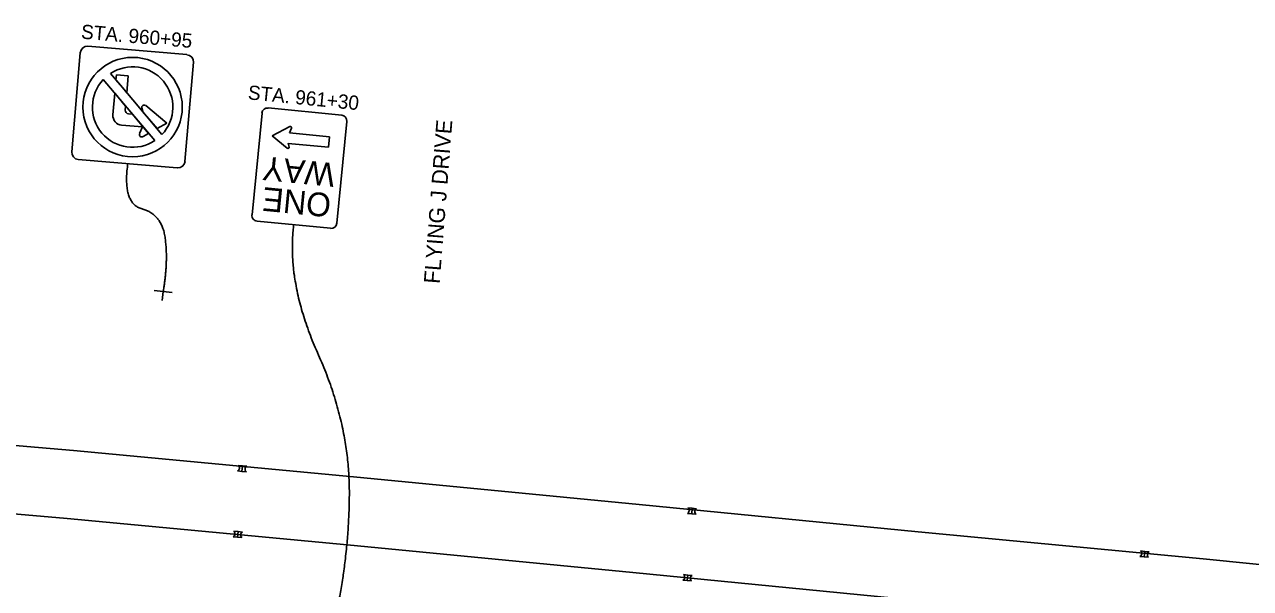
# Model space of a CAD drawing. Extents: x 1847379 to 1850904, y 217032 to 220169.
# Drawn here: x 1850210.2 to 1850426.1, y 218769.3 to 218868.6 of the extents above; entities that cross this region are included whole.
import ezdxf

# ---------------------------------------------------------------- set-up
doc = ezdxf.new("R2010")
doc.units = 0
for name, color, linetype in [('PM_P_Cells', 7, 'Continuous'), ('PM_P_Edge_Line', 7, 'Continuous'), ('PM_P_Lane_Line', 7, 'Continuous'), ('SN_X_Public', 7, 'Continuous'), ('SN_X_Text', 7, 'Continuous')]:
    doc.layers.add(name, color=color, linetype=linetype)

msp = doc.modelspace()

# ---------------------------------------------------------------- linework, layer by layer
at = {"layer": 'PM_P_Cells'}
for p, q in [((1850247.75, 218790.01), (1850248.51, 218789.94)), ((1850247.75, 218790.01), (1850248.51, 218789.94)), ((1850248.6, 218790.91), (1850247.83, 218790.98)), ((1850247.83, 218790.98), (1850248.6, 218790.91)), ((1850248.51, 218789.94), (1850248.6, 218790.91)), ((1850248.51, 218789.94), (1850249.28, 218789.87)), ((1850248.6, 218790.91), (1850249.37, 218790.84)), ((1850327.78, 218783.43), (1850327.01, 218783.5)), ((1850327.01, 218783.5), (1850327.78, 218783.43)), ((1850327.69, 218782.45), (1850327.78, 218783.43)), ((1850327.78, 218783.43), (1850328.55, 218783.36)), ((1850326.92, 218782.52), (1850327.69, 218782.45)), ((1850326.92, 218782.52), (1850327.69, 218782.45)), ((1850327.69, 218782.45), (1850328.46, 218782.39)), ((1850247.83, 218779.33), (1850247.06, 218779.4)), ((1850247.06, 218779.4), (1850247.83, 218779.33)), ((1850247.74, 218778.36), (1850247.83, 218779.33)), ((1850247.83, 218779.33), (1850248.6, 218779.26)), ((1850246.97, 218778.42), (1850247.74, 218778.36)), ((1850246.97, 218778.42), (1850247.74, 218778.36)), ((1850247.74, 218778.36), (1850248.51, 218778.29)), ((1850406.6, 218774.95), (1850407.36, 218774.88)), ((1850406.6, 218774.95), (1850407.36, 218774.88)), ((1850407.45, 218775.85), (1850406.68, 218775.92)), ((1850406.68, 218775.92), (1850407.45, 218775.85)), ((1850407.36, 218774.88), (1850407.45, 218775.85)), ((1850407.36, 218774.88), (1850408.13, 218774.81)), ((1850407.45, 218775.85), (1850408.22, 218775.78)), ((1850326.14, 218770.79), (1850326.91, 218770.72)), ((1850326.14, 218770.79), (1850326.91, 218770.72)), ((1850327, 218771.69), (1850326.23, 218771.76)), ((1850326.23, 218771.76), (1850327, 218771.69)), ((1850326.91, 218770.72), (1850327, 218771.69)), ((1850326.91, 218770.72), (1850327.67, 218770.65)), ((1850327, 218771.69), (1850327.76, 218771.62))]:
    msp.add_line(p, q, dxfattribs=at)
for centre, start, end in [((1850247.49, 218790.52), 296.8063, 52.8586), ((1850247.49, 218790.52), 296.8063, 52.8586), ((1850249.63, 218790.33), 116.8063, 232.8586), ((1850326.66, 218783.04), 296.8063, 52.8586), ((1850326.66, 218783.04), 296.8063, 52.8586), ((1850328.81, 218782.84), 116.8063, 232.8586), ((1850246.71, 218778.94), 296.8063, 52.8586), ((1850246.71, 218778.94), 296.8063, 52.8586), ((1850248.86, 218778.74), 116.8063, 232.8586), ((1850406.34, 218775.46), 296.8063, 52.8586), ((1850406.34, 218775.46), 296.8063, 52.8586), ((1850408.48, 218775.27), 116.8063, 232.8586), ((1850325.88, 218771.3), 296.8063, 52.8586), ((1850325.88, 218771.3), 296.8063, 52.8586), ((1850328.02, 218771.11), 116.8063, 232.8586)]:
    msp.add_arc(centre, 0.576, start, end, dxfattribs=at)
at = {"layer": 'PM_P_Edge_Line'}
msp.add_lwpolyline([(1849889.22, 218821.46), (1849908.57, 218819.63), (1849959.34, 218815.75), (1850016.54, 218811.11), (1850069.2, 218806.62), (1850120.11, 218802.11), (1850169.53, 218797.86), (1850218.84, 218793.6), (1850268.16, 218788.98), (1850318.46, 218784.1), (1850367.53, 218779.29), (1850417.75, 218774.53), (1850467.84, 218769.49), (1850519.01, 218764.5), (1850567.74, 218759.83), (1850617.52, 218754.84), (1850666.94, 218749.6)], dxfattribs=at)
at = {"layer": 'PM_P_Lane_Line'}
msp.add_lwpolyline([(1849608.99, 218828.81), (1849660.31, 218825.18), (1849710.18, 218821.58), (1849761.09, 218817.87), (1849808.06, 218814.41), (1849858.45, 218811.1), (1849907.69, 218807.67), (1849958.4, 218803.79), (1850015.55, 218799.15), (1850068.16, 218794.66), (1850119.07, 218790.16), (1850168.5, 218785.91), (1850217.76, 218781.65), (1850267.02, 218777.03), (1850317.3, 218772.15), (1850366.38, 218767.35), (1850416.59, 218762.59), (1850466.65, 218757.55), (1850517.86, 218752.55), (1850566.57, 218747.88), (1850616.29, 218742.91), (1850664.9, 218737.75)], dxfattribs=at)
at = {"layer": 'SN_X_Public'}
for p, q in [((1850233.16, 218848.15), (1850224.09, 218858.9)), ((1850226.32, 218858.84), (1850226.4, 218859.74)), ((1850226.4, 218859.74), (1850226.32, 218858.84)), ((1850226.32, 218858.84), (1850227.45, 218857.51)), ((1850226.4, 218859.74), (1850228.47, 218859.57)), ((1850228.47, 218859.57), (1850226.4, 218859.74)), ((1850228.22, 218856.59), (1850228.47, 218859.57)), ((1850228.22, 218856.59), (1850228.47, 218859.57)), ((1850227.45, 218857.51), (1850228.22, 218856.59)), ((1850225.8, 218852.68), (1850226.12, 218856.49)), ((1850226.12, 218856.49), (1850225.8, 218852.68)), ((1850226.17, 218856.43), (1850226.12, 218856.49)), ((1850228.02, 218854.24), (1850226.17, 218856.43)), ((1850227.96, 218853.52), (1850228.02, 218854.24)), ((1850227.96, 218853.52), (1850228.02, 218854.24)), ((1850228.51, 218852.87), (1850229.23, 218852.81)), ((1850229.23, 218852.81), (1850228.51, 218852.87)), ((1850232.08, 218849.42), (1850229.23, 218852.81)), ((1850230.89, 218853.9), (1850231.03, 218853.28)), ((1850230.89, 218853.9), (1850231.03, 218853.28)), ((1850231.02, 218853.27), (1850233.56, 218850.26)), ((1850231.56, 218854.32), (1850235.29, 218851.25)), ((1850235.29, 218851.25), (1850231.56, 218854.32)), ((1850250.28, 218835.08), (1850252.04, 218853)), ((1850253.13, 218853.9), (1850266.07, 218852.62)), ((1850227.32, 218850.88), (1850230.99, 218850.57)), ((1850227.32, 218850.88), (1850230.99, 218850.57)), ((1850230.5, 218849.38), (1850230.99, 218850.57)), ((1850230.99, 218850.57), (1850230.5, 218849.38)), ((1850233.56, 218850.26), (1850235.29, 218851.25)), ((1850233.56, 218850.26), (1850235.29, 218851.25)), ((1850253.85, 218848.97), (1850256.93, 218850.62)), ((1850257.22, 218850.35), (1850256.86, 218849.54)), ((1850266.97, 218851.53), (1850265.2, 218833.62)), ((1850231.09, 218848.86), (1850232.08, 218849.42)), ((1850231.09, 218848.86), (1850232.08, 218849.42)), ((1850256.48, 218846.82), (1850253.85, 218848.97)), ((1850256.86, 218849.54), (1850263.91, 218848.84)), ((1850263.91, 218848.84), (1850263.73, 218846.98)), ((1850256.66, 218847.69), (1850256.82, 218847.03)), ((1850263.73, 218846.98), (1850256.66, 218847.67)), ((1850264.11, 218832.72), (1850251.17, 218833.99)), ((1850233.05, 218821.75), (1850236.24, 218821.45)), ((1850234.65, 218821.6), (1850234.49, 218820.01))]:
    msp.add_line(p, q, dxfattribs=at)
for points in [[(1850218.56, 218846.19), (1850220.04, 218863.63)], [(1850221.39, 218864.77), (1850238.83, 218863.29)], [(1850239.97, 218861.94), (1850238.48, 218844.5)], [(1850227.45, 218857.51), (1850225.36, 218859.98)], [(1850234.43, 218849.22), (1850229.3, 218855.31), (1850227.45, 218857.51)], [(1850231.03, 218853.28), (1850231.02, 218853.27)], [(1850237.13, 218843.36), (1850219.7, 218844.84)]]:
    msp.add_lwpolyline(points, dxfattribs=at)
msp.add_circle((1850229.26, 218854.06), 8.75, dxfattribs=at)
for centre, radius, start, end in [((1850221.28, 218863.52), 1.25, 85.1482, 175.1482), ((1850238.72, 218862.04), 1.25, 355.1482, 85.1482), ((1850229.26, 218854.06), 7.08, 316.9045, 123.3918), ((1850229.26, 218854.06), 7.08, 316.9045, 123.3918), ((1850229.26, 218854.06), 7.08, 136.9045, 303.3918), ((1850227.46, 218852.54), 1.67, 175.1482, 265.1482), ((1850227.46, 218852.54), 1.67, 175.1482, 265.1482), ((1850228.56, 218853.47), 0.6, 175.1482, 265.1482), ((1850228.56, 218853.47), 0.6, 175.1482, 265.1482), ((1850231.29, 218853.99), 0.417, 50.6319, 192.51), ((1850231.29, 218853.99), 0.417, 50.6319, 192.51), ((1850253.03, 218852.9), 1, 84.3781, 174.3781), ((1850265.97, 218851.63), 1, 354.3781, 84.3781), ((1850257.03, 218850.43), 0.208, 336.4547, 118.1036), ((1850230.89, 218849.22), 0.417, 157.7863, 299.6644), ((1850230.89, 218849.22), 0.417, 157.7863, 299.6644), ((1850219.8, 218846.08), 1.25, 175.1482, 265.1482), ((1850256.62, 218846.98), 0.208, 230.8022, 13.4415), ((1850237.24, 218844.6), 1.25, 265.1482, 355.1482), ((1850251.27, 218834.99), 1, 174.3781, 264.3781), ((1850264.21, 218833.71), 1, 264.3781, 354.3781)]:
    msp.add_arc(centre, radius, start, end, dxfattribs=at)
at = {"layer": 'SN_X_Text'}
for points in [[(1850234.65, 218821.6), (1850235.55, 218826.86), (1850234.42, 218835.18), (1850227.43, 218837.1), (1850228.41, 218844.1)], [(1850264.35, 218761.83), (1850267.28, 218773.2), (1850267.55, 218798.02), (1850256.3, 218823.1), (1850257.64, 218833.35)]]:
    msp.add_open_spline(points, degree=2, dxfattribs=at)

# ---------------------------------------------------------------- texts
at = {"layer": 'SN_X_Public'}
for s, height, rotation, p in [('FLYING J DRIVE', 2.8, 85.5355, (1850283.31, 218822.89)), ('WAY', 4.172, 174.3781, (1850265.02, 218844.15)), ('ONE', 4.172, 174.3781, (1850264.36, 218838.8))]:
    msp.add_text(s, height=height, rotation=rotation, dxfattribs=at).set_placement(p)
at = {"layer": 'SN_X_Text'}
for s, rotation, p in [('STA. 960+95', 355.1482, (1850220.11, 218866.12)), ('STA. 961+30', 354.3781, (1850249.47, 218855.43))]:
    msp.add_text(s, height=2.5, rotation=rotation, dxfattribs=at).set_placement(p)

doc.saveas('drawing.dxf')
